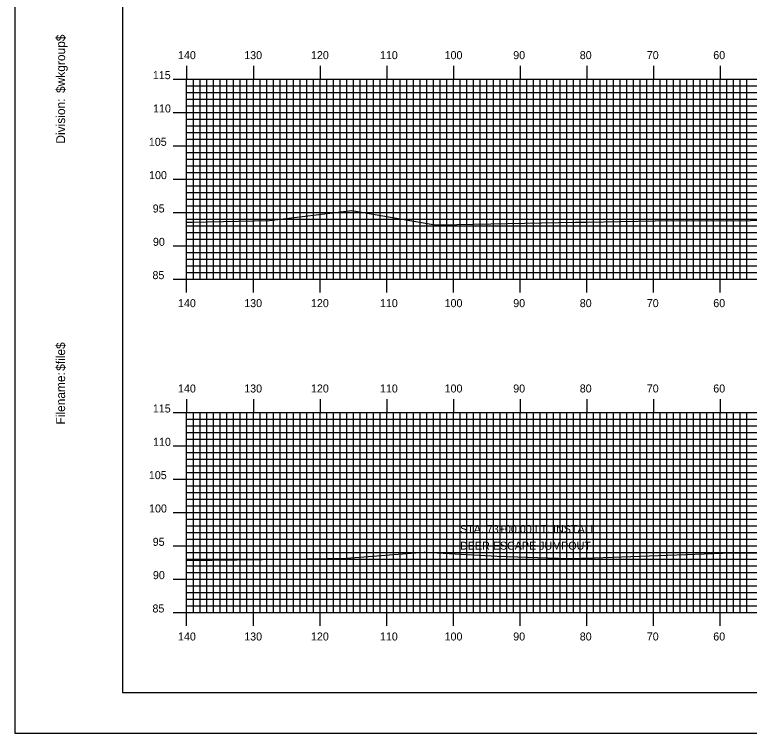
# Model space of a CAD drawing. Extents: x 1761004 to 1761347, y 442591 to 442811.
# Drawn here: x 1761003.9 to 1761114.1, y 442590.5 to 442698.3 of the extents above; entities that cross this region are included whole.
import ezdxf

# ---------------------------------------------------------------- set-up
doc = ezdxf.new("R2010")
doc.units = 0
for name, color, linetype in [('BORDER', 7, 'Continuous'), ('D_Text_Standard', 7, 'Continuous'), ('H_V ANNOTATION', 7, 'Continuous'), ('MAJOR', 7, 'Continuous'), ('MINOR', 7, 'Continuous'), ('PLOT BOUNDARY', 7, 'Continuous'), ('S_Roadway_Centerline', 7, 'Continuous')]:
    doc.layers.add(name, color=color, linetype=linetype)

msp = doc.modelspace()

# ---------------------------------------------------------------- linework, layer by layer
at = {"layer": 'BORDER'}
msp.add_lwpolyline([(1761020.13, 442596.67), (1761340.13, 442596.67), (1761340.13, 442806.67), (1761020.13, 442806.67)], close=True, dxfattribs=at)
at = {"layer": 'MAJOR'}
for p, q in [((1761029.73, 442690.67), (1761029.73, 442688.67)), ((1761039.73, 442690.67), (1761039.73, 442688.67)), ((1761049.73, 442690.67), (1761049.73, 442688.67)), ((1761059.73, 442690.67), (1761059.73, 442688.67)), ((1761069.73, 442690.67), (1761069.73, 442688.67)), ((1761079.73, 442690.67), (1761079.73, 442688.67)), ((1761089.73, 442690.67), (1761089.73, 442688.67)), ((1761099.73, 442690.67), (1761099.73, 442688.67)), ((1761109.73, 442690.67), (1761109.73, 442688.67)), ((1761027.72, 442688.67), (1761029.73, 442688.67)), ((1761029.73, 442688.67), (1761309.73, 442688.67)), ((1761029.73, 442658.67), (1761029.73, 442688.67)), ((1761029.73, 442658.67), (1761029.73, 442688.67)), ((1761029.73, 442688.67), (1761309.73, 442688.67)), ((1761039.73, 442658.67), (1761039.73, 442688.67)), ((1761049.73, 442658.67), (1761049.73, 442688.67)), ((1761059.73, 442658.67), (1761059.73, 442688.67)), ((1761069.73, 442658.67), (1761069.73, 442688.67)), ((1761079.73, 442658.67), (1761079.73, 442688.67)), ((1761089.73, 442658.67), (1761089.73, 442688.67)), ((1761099.73, 442658.67), (1761099.73, 442688.67)), ((1761109.73, 442658.67), (1761109.73, 442688.67)), ((1761027.72, 442683.67), (1761029.73, 442683.67)), ((1761029.73, 442683.67), (1761309.73, 442683.67)), ((1761027.72, 442678.67), (1761029.73, 442678.67)), ((1761029.73, 442678.67), (1761309.73, 442678.67)), ((1761027.72, 442673.67), (1761029.73, 442673.67)), ((1761029.73, 442673.67), (1761309.73, 442673.67)), ((1761027.72, 442668.67), (1761029.73, 442668.67)), ((1761029.73, 442668.67), (1761309.73, 442668.67)), ((1761027.72, 442663.67), (1761029.73, 442663.67)), ((1761029.73, 442663.67), (1761309.73, 442663.67)), ((1761027.72, 442658.67), (1761029.73, 442658.67)), ((1761029.73, 442658.67), (1761309.73, 442658.67)), ((1761029.73, 442658.67), (1761309.73, 442658.67)), ((1761029.73, 442656.66), (1761029.73, 442658.67)), ((1761039.73, 442656.66), (1761039.73, 442658.67)), ((1761049.73, 442656.66), (1761049.73, 442658.67)), ((1761059.73, 442656.66), (1761059.73, 442658.67)), ((1761069.73, 442656.66), (1761069.73, 442658.67)), ((1761079.73, 442656.66), (1761079.73, 442658.67)), ((1761089.73, 442656.66), (1761089.73, 442658.67)), ((1761099.73, 442656.66), (1761099.73, 442658.67)), ((1761109.73, 442656.66), (1761109.73, 442658.67)), ((1761029.73, 442640.67), (1761029.73, 442638.67)), ((1761039.73, 442640.67), (1761039.73, 442638.67)), ((1761049.73, 442640.67), (1761049.73, 442638.67)), ((1761059.73, 442640.67), (1761059.73, 442638.67)), ((1761069.73, 442640.67), (1761069.73, 442638.67)), ((1761079.73, 442640.67), (1761079.73, 442638.67)), ((1761089.73, 442640.67), (1761089.73, 442638.67)), ((1761099.73, 442640.67), (1761099.73, 442638.67)), ((1761109.73, 442640.67), (1761109.73, 442638.67)), ((1761027.72, 442638.67), (1761029.73, 442638.67)), ((1761029.73, 442638.67), (1761309.73, 442638.67)), ((1761029.73, 442608.67), (1761029.73, 442638.67)), ((1761029.73, 442608.67), (1761029.73, 442638.67)), ((1761029.73, 442638.67), (1761309.73, 442638.67)), ((1761039.73, 442608.67), (1761039.73, 442638.67)), ((1761049.73, 442608.67), (1761049.73, 442638.67)), ((1761059.73, 442608.67), (1761059.73, 442638.67)), ((1761069.73, 442608.67), (1761069.73, 442638.67)), ((1761079.73, 442608.67), (1761079.73, 442638.67)), ((1761089.73, 442608.67), (1761089.73, 442638.67)), ((1761099.73, 442608.67), (1761099.73, 442638.67)), ((1761109.73, 442608.67), (1761109.73, 442638.67)), ((1761027.72, 442633.67), (1761029.73, 442633.67)), ((1761029.73, 442633.67), (1761309.73, 442633.67)), ((1761027.72, 442628.67), (1761029.73, 442628.67)), ((1761029.73, 442628.67), (1761309.73, 442628.67)), ((1761027.72, 442623.67), (1761029.73, 442623.67)), ((1761029.73, 442623.67), (1761309.73, 442623.67)), ((1761027.72, 442618.67), (1761029.73, 442618.67)), ((1761029.73, 442618.67), (1761309.73, 442618.67)), ((1761027.72, 442613.67), (1761029.73, 442613.67)), ((1761029.73, 442613.67), (1761309.73, 442613.67)), ((1761027.72, 442608.67), (1761029.73, 442608.67)), ((1761029.73, 442608.67), (1761309.73, 442608.67)), ((1761029.73, 442608.67), (1761309.73, 442608.67)), ((1761029.73, 442606.66), (1761029.73, 442608.67)), ((1761039.73, 442606.66), (1761039.73, 442608.67)), ((1761049.73, 442606.66), (1761049.73, 442608.67)), ((1761059.73, 442606.66), (1761059.73, 442608.67)), ((1761069.73, 442606.66), (1761069.73, 442608.67)), ((1761079.73, 442606.66), (1761079.73, 442608.67)), ((1761089.73, 442606.66), (1761089.73, 442608.67)), ((1761099.73, 442606.66), (1761099.73, 442608.67)), ((1761109.73, 442606.66), (1761109.73, 442608.67))]:
    msp.add_line(p, q, dxfattribs=at)
at = {"layer": 'MINOR'}
for p, q in [((1761030.73, 442658.67), (1761030.73, 442688.67)), ((1761031.73, 442658.67), (1761031.73, 442688.67)), ((1761032.73, 442658.67), (1761032.73, 442688.67)), ((1761033.73, 442658.67), (1761033.73, 442688.67)), ((1761034.73, 442658.67), (1761034.73, 442688.67)), ((1761035.73, 442658.67), (1761035.73, 442688.67)), ((1761036.73, 442658.67), (1761036.73, 442688.67)), ((1761037.73, 442658.67), (1761037.73, 442688.67)), ((1761038.73, 442658.67), (1761038.73, 442688.67)), ((1761040.73, 442658.67), (1761040.73, 442688.67)), ((1761041.73, 442658.67), (1761041.73, 442688.67)), ((1761042.73, 442658.67), (1761042.73, 442688.67)), ((1761043.73, 442658.67), (1761043.73, 442688.67)), ((1761044.73, 442658.67), (1761044.73, 442688.67)), ((1761045.73, 442658.67), (1761045.73, 442688.67)), ((1761046.73, 442658.67), (1761046.73, 442688.67)), ((1761047.73, 442658.67), (1761047.73, 442688.67)), ((1761048.73, 442658.67), (1761048.73, 442688.67)), ((1761050.73, 442658.67), (1761050.73, 442688.67)), ((1761051.73, 442658.67), (1761051.73, 442688.67)), ((1761052.73, 442658.67), (1761052.73, 442688.67)), ((1761053.73, 442658.67), (1761053.73, 442688.67)), ((1761054.73, 442658.67), (1761054.73, 442688.67)), ((1761055.73, 442658.67), (1761055.73, 442688.67)), ((1761056.73, 442658.67), (1761056.73, 442688.67)), ((1761057.73, 442658.67), (1761057.73, 442688.67)), ((1761058.73, 442658.67), (1761058.73, 442688.67)), ((1761060.73, 442658.67), (1761060.73, 442688.67)), ((1761061.73, 442658.67), (1761061.73, 442688.67)), ((1761062.73, 442658.67), (1761062.73, 442688.67)), ((1761063.73, 442658.67), (1761063.73, 442688.67)), ((1761064.73, 442658.67), (1761064.73, 442688.67)), ((1761065.73, 442658.67), (1761065.73, 442688.67)), ((1761066.73, 442658.67), (1761066.73, 442688.67)), ((1761067.73, 442658.67), (1761067.73, 442688.67)), ((1761068.73, 442658.67), (1761068.73, 442688.67)), ((1761070.73, 442658.67), (1761070.73, 442688.67)), ((1761071.73, 442658.67), (1761071.73, 442688.67)), ((1761072.73, 442658.67), (1761072.73, 442688.67)), ((1761073.73, 442658.67), (1761073.73, 442688.67)), ((1761074.73, 442658.67), (1761074.73, 442688.67)), ((1761075.73, 442658.67), (1761075.73, 442688.67)), ((1761076.73, 442658.67), (1761076.73, 442688.67)), ((1761077.73, 442658.67), (1761077.73, 442688.67)), ((1761078.73, 442658.67), (1761078.73, 442688.67)), ((1761080.73, 442658.67), (1761080.73, 442688.67)), ((1761081.73, 442658.67), (1761081.73, 442688.67)), ((1761082.73, 442658.67), (1761082.73, 442688.67)), ((1761083.73, 442658.67), (1761083.73, 442688.67)), ((1761084.73, 442658.67), (1761084.73, 442688.67)), ((1761085.73, 442658.67), (1761085.73, 442688.67)), ((1761086.73, 442658.67), (1761086.73, 442688.67)), ((1761087.73, 442658.67), (1761087.73, 442688.67)), ((1761088.73, 442658.67), (1761088.73, 442688.67)), ((1761090.73, 442658.67), (1761090.73, 442688.67)), ((1761091.73, 442658.67), (1761091.73, 442688.67)), ((1761092.73, 442658.67), (1761092.73, 442688.67)), ((1761093.73, 442658.67), (1761093.73, 442688.67)), ((1761094.73, 442658.67), (1761094.73, 442688.67)), ((1761095.73, 442658.67), (1761095.73, 442688.67)), ((1761096.73, 442658.67), (1761096.73, 442688.67)), ((1761097.73, 442658.67), (1761097.73, 442688.67)), ((1761098.73, 442658.67), (1761098.73, 442688.67)), ((1761100.73, 442658.67), (1761100.73, 442688.67)), ((1761101.73, 442658.67), (1761101.73, 442688.67)), ((1761102.73, 442658.67), (1761102.73, 442688.67)), ((1761103.73, 442658.67), (1761103.73, 442688.67)), ((1761104.73, 442658.67), (1761104.73, 442688.67)), ((1761105.73, 442658.67), (1761105.73, 442688.67)), ((1761106.73, 442658.67), (1761106.73, 442688.67)), ((1761107.73, 442658.67), (1761107.73, 442688.67)), ((1761108.73, 442658.67), (1761108.73, 442688.67)), ((1761110.73, 442658.67), (1761110.73, 442688.67)), ((1761111.73, 442658.67), (1761111.73, 442688.67)), ((1761112.73, 442658.67), (1761112.73, 442688.67)), ((1761113.73, 442658.67), (1761113.73, 442688.67)), ((1761029.73, 442687.67), (1761309.73, 442687.67)), ((1761029.73, 442687.67), (1761031.73, 442687.67)), ((1761029.73, 442686.67), (1761309.73, 442686.67)), ((1761029.73, 442686.67), (1761031.73, 442686.67)), ((1761029.73, 442685.67), (1761309.73, 442685.67)), ((1761029.73, 442685.67), (1761031.73, 442685.67)), ((1761029.73, 442684.67), (1761309.73, 442684.67)), ((1761029.73, 442684.67), (1761031.73, 442684.67)), ((1761029.73, 442682.67), (1761309.73, 442682.67)), ((1761029.73, 442682.67), (1761031.73, 442682.67)), ((1761029.73, 442681.67), (1761309.73, 442681.67)), ((1761029.73, 442681.67), (1761031.73, 442681.67)), ((1761029.73, 442680.67), (1761309.73, 442680.67)), ((1761029.73, 442680.67), (1761031.73, 442680.67)), ((1761029.73, 442679.67), (1761309.73, 442679.67)), ((1761029.73, 442679.67), (1761031.73, 442679.67)), ((1761029.73, 442677.67), (1761309.73, 442677.67)), ((1761029.73, 442677.67), (1761031.73, 442677.67)), ((1761029.73, 442676.67), (1761309.73, 442676.67)), ((1761029.73, 442676.67), (1761031.73, 442676.67)), ((1761029.73, 442675.67), (1761309.73, 442675.67)), ((1761029.73, 442675.67), (1761031.73, 442675.67)), ((1761029.73, 442674.67), (1761309.73, 442674.67)), ((1761029.73, 442674.67), (1761031.73, 442674.67)), ((1761029.73, 442672.67), (1761309.73, 442672.67)), ((1761029.73, 442672.67), (1761031.73, 442672.67)), ((1761029.73, 442671.67), (1761309.73, 442671.67)), ((1761029.73, 442671.67), (1761031.73, 442671.67)), ((1761029.73, 442670.67), (1761309.73, 442670.67)), ((1761029.73, 442670.67), (1761031.73, 442670.67)), ((1761029.73, 442669.67), (1761309.73, 442669.67)), ((1761029.73, 442669.67), (1761031.73, 442669.67)), ((1761029.73, 442667.67), (1761309.73, 442667.67)), ((1761029.73, 442667.67), (1761031.73, 442667.67)), ((1761029.73, 442666.67), (1761309.73, 442666.67)), ((1761029.73, 442666.67), (1761031.73, 442666.67)), ((1761029.73, 442665.67), (1761309.73, 442665.67)), ((1761029.73, 442665.67), (1761031.73, 442665.67)), ((1761029.73, 442664.67), (1761309.73, 442664.67)), ((1761029.73, 442664.67), (1761031.73, 442664.67)), ((1761029.73, 442662.67), (1761309.73, 442662.67)), ((1761029.73, 442662.67), (1761031.73, 442662.67)), ((1761029.73, 442661.67), (1761309.73, 442661.67)), ((1761029.73, 442661.67), (1761031.73, 442661.67)), ((1761029.73, 442660.67), (1761309.73, 442660.67)), ((1761029.73, 442660.67), (1761031.73, 442660.67)), ((1761029.73, 442659.67), (1761309.73, 442659.67)), ((1761029.73, 442659.67), (1761031.73, 442659.67)), ((1761030.73, 442608.67), (1761030.73, 442638.67)), ((1761031.73, 442608.67), (1761031.73, 442638.67)), ((1761032.73, 442608.67), (1761032.73, 442638.67)), ((1761033.73, 442608.67), (1761033.73, 442638.67)), ((1761034.73, 442608.67), (1761034.73, 442638.67)), ((1761035.73, 442608.67), (1761035.73, 442638.67)), ((1761036.73, 442608.67), (1761036.73, 442638.67)), ((1761037.73, 442608.67), (1761037.73, 442638.67)), ((1761038.73, 442608.67), (1761038.73, 442638.67)), ((1761040.73, 442608.67), (1761040.73, 442638.67)), ((1761041.73, 442608.67), (1761041.73, 442638.67)), ((1761042.73, 442608.67), (1761042.73, 442638.67)), ((1761043.73, 442608.67), (1761043.73, 442638.67)), ((1761044.73, 442608.67), (1761044.73, 442638.67)), ((1761045.73, 442608.67), (1761045.73, 442638.67)), ((1761046.73, 442608.67), (1761046.73, 442638.67)), ((1761047.73, 442608.67), (1761047.73, 442638.67)), ((1761048.73, 442608.67), (1761048.73, 442638.67)), ((1761050.73, 442608.67), (1761050.73, 442638.67)), ((1761051.73, 442608.67), (1761051.73, 442638.67)), ((1761052.73, 442608.67), (1761052.73, 442638.67)), ((1761053.73, 442608.67), (1761053.73, 442638.67)), ((1761054.73, 442608.67), (1761054.73, 442638.67)), ((1761055.73, 442608.67), (1761055.73, 442638.67)), ((1761056.73, 442608.67), (1761056.73, 442638.67)), ((1761057.73, 442608.67), (1761057.73, 442638.67)), ((1761058.73, 442608.67), (1761058.73, 442638.67)), ((1761060.73, 442608.67), (1761060.73, 442638.67)), ((1761061.73, 442608.67), (1761061.73, 442638.67)), ((1761062.73, 442608.67), (1761062.73, 442638.67)), ((1761063.73, 442608.67), (1761063.73, 442638.67)), ((1761064.73, 442608.67), (1761064.73, 442638.67)), ((1761065.73, 442608.67), (1761065.73, 442638.67)), ((1761066.73, 442608.67), (1761066.73, 442638.67)), ((1761067.73, 442608.67), (1761067.73, 442638.67)), ((1761068.73, 442608.67), (1761068.73, 442638.67)), ((1761070.73, 442608.67), (1761070.73, 442638.67)), ((1761071.73, 442608.67), (1761071.73, 442638.67)), ((1761072.73, 442608.67), (1761072.73, 442638.67)), ((1761073.73, 442608.67), (1761073.73, 442638.67)), ((1761074.73, 442608.67), (1761074.73, 442638.67)), ((1761075.73, 442608.67), (1761075.73, 442638.67)), ((1761076.73, 442608.67), (1761076.73, 442638.67)), ((1761077.73, 442608.67), (1761077.73, 442638.67)), ((1761078.73, 442608.67), (1761078.73, 442638.67)), ((1761080.73, 442608.67), (1761080.73, 442638.67)), ((1761081.73, 442608.67), (1761081.73, 442638.67)), ((1761082.73, 442608.67), (1761082.73, 442638.67)), ((1761083.73, 442608.67), (1761083.73, 442638.67)), ((1761084.73, 442608.67), (1761084.73, 442638.67)), ((1761085.73, 442608.67), (1761085.73, 442638.67)), ((1761086.73, 442608.67), (1761086.73, 442638.67)), ((1761087.73, 442608.67), (1761087.73, 442638.67)), ((1761088.73, 442608.67), (1761088.73, 442638.67)), ((1761090.73, 442608.67), (1761090.73, 442638.67)), ((1761091.73, 442608.67), (1761091.73, 442638.67)), ((1761092.73, 442608.67), (1761092.73, 442638.67)), ((1761093.73, 442608.67), (1761093.73, 442638.67)), ((1761094.73, 442608.67), (1761094.73, 442638.67)), ((1761095.73, 442608.67), (1761095.73, 442638.67)), ((1761096.73, 442608.67), (1761096.73, 442638.67)), ((1761097.73, 442608.67), (1761097.73, 442638.67)), ((1761098.73, 442608.67), (1761098.73, 442638.67)), ((1761100.73, 442608.67), (1761100.73, 442638.67)), ((1761101.73, 442608.67), (1761101.73, 442638.67)), ((1761102.73, 442608.67), (1761102.73, 442638.67)), ((1761103.73, 442608.67), (1761103.73, 442638.67)), ((1761104.73, 442608.67), (1761104.73, 442638.67)), ((1761105.73, 442608.67), (1761105.73, 442638.67)), ((1761106.73, 442608.67), (1761106.73, 442638.67)), ((1761107.73, 442608.67), (1761107.73, 442638.67)), ((1761108.73, 442608.67), (1761108.73, 442638.67)), ((1761110.73, 442608.67), (1761110.73, 442638.67)), ((1761111.73, 442608.67), (1761111.73, 442638.67)), ((1761112.73, 442608.67), (1761112.73, 442638.67)), ((1761113.73, 442608.67), (1761113.73, 442638.67)), ((1761029.73, 442637.67), (1761309.73, 442637.67)), ((1761029.73, 442637.67), (1761031.73, 442637.67)), ((1761029.73, 442636.67), (1761309.73, 442636.67)), ((1761029.73, 442636.67), (1761031.73, 442636.67)), ((1761029.73, 442635.67), (1761309.73, 442635.67)), ((1761029.73, 442635.67), (1761031.73, 442635.67)), ((1761029.73, 442634.67), (1761309.73, 442634.67)), ((1761029.73, 442634.67), (1761031.73, 442634.67)), ((1761029.73, 442632.67), (1761309.73, 442632.67)), ((1761029.73, 442632.67), (1761031.73, 442632.67)), ((1761029.73, 442631.67), (1761309.73, 442631.67)), ((1761029.73, 442631.67), (1761031.73, 442631.67)), ((1761029.73, 442630.67), (1761309.73, 442630.67)), ((1761029.73, 442630.67), (1761031.73, 442630.67)), ((1761029.73, 442629.67), (1761309.73, 442629.67)), ((1761029.73, 442629.67), (1761031.73, 442629.67)), ((1761029.73, 442627.67), (1761309.73, 442627.67)), ((1761029.73, 442627.67), (1761031.73, 442627.67)), ((1761029.73, 442626.67), (1761309.73, 442626.67)), ((1761029.73, 442626.67), (1761031.73, 442626.67)), ((1761029.73, 442625.67), (1761309.73, 442625.67)), ((1761029.73, 442625.67), (1761031.73, 442625.67)), ((1761029.73, 442624.67), (1761309.73, 442624.67)), ((1761029.73, 442624.67), (1761031.73, 442624.67)), ((1761029.73, 442622.67), (1761309.73, 442622.67)), ((1761029.73, 442622.67), (1761031.73, 442622.67)), ((1761029.73, 442621.67), (1761309.73, 442621.67)), ((1761029.73, 442621.67), (1761031.73, 442621.67)), ((1761029.73, 442620.67), (1761309.73, 442620.67)), ((1761029.73, 442620.67), (1761031.73, 442620.67)), ((1761029.73, 442619.67), (1761309.73, 442619.67)), ((1761029.73, 442619.67), (1761031.73, 442619.67)), ((1761029.73, 442617.67), (1761309.73, 442617.67)), ((1761029.73, 442617.67), (1761031.73, 442617.67)), ((1761029.73, 442616.67), (1761309.73, 442616.67)), ((1761029.73, 442616.67), (1761031.73, 442616.67)), ((1761029.73, 442615.67), (1761309.73, 442615.67)), ((1761029.73, 442615.67), (1761031.73, 442615.67)), ((1761029.73, 442614.67), (1761309.73, 442614.67)), ((1761029.73, 442614.67), (1761031.73, 442614.67)), ((1761029.73, 442612.67), (1761309.73, 442612.67)), ((1761029.73, 442612.67), (1761031.73, 442612.67)), ((1761029.73, 442611.67), (1761309.73, 442611.67)), ((1761029.73, 442611.67), (1761031.73, 442611.67)), ((1761029.73, 442610.67), (1761309.73, 442610.67)), ((1761029.73, 442610.67), (1761031.73, 442610.67)), ((1761029.73, 442609.67), (1761309.73, 442609.67)), ((1761029.73, 442609.67), (1761031.73, 442609.67))]:
    msp.add_line(p, q, dxfattribs=at)
at = {"layer": 'PLOT BOUNDARY'}
msp.add_lwpolyline([(1761003.94, 442590.55), (1761343.94, 442590.55), (1761343.94, 442810.55), (1761003.94, 442810.55)], close=True, dxfattribs=at)
at = {"layer": 'S_Roadway_Centerline'}
for points in [[(1761029.73, 442667.21), (1761030.55, 442667.21), (1761042.13, 442667.45), (1761042.14, 442667.45), (1761042.15, 442667.45), (1761054.5, 442668.98), (1761066.71, 442666.85), (1761067.18, 442666.8), (1761067.71, 442666.8), (1761088.06, 442667.2), (1761088.96, 442667.24), (1761089.68, 442667.22), (1761099.97, 442667.41), (1761111.24, 442667.45), (1761112.76, 442667.42), (1761132.26, 442668.06)], [(1761029.73, 442616.46), (1761041.03, 442616.64), (1761041.39, 442616.65), (1761041.79, 442616.64), (1761053.69, 442616.81), (1761065.33, 442617.71), (1761065.43, 442617.72), (1761065.51, 442617.71), (1761076.28, 442617.12), (1761086.93, 442616.75), (1761090.84, 442616.86), (1761110.11, 442617.56), (1761112.77, 442617.6), (1761122.62, 442617.53)]]:
    msp.add_lwpolyline(points, dxfattribs=at)

# ---------------------------------------------------------------- texts
at = {"layer": 'BORDER'}
for s, p in [('$wkgroup$', (1761011.5, 442686.6)), ('Division:', (1761011.5, 442679)), ('$file$', (1761011.5, 442644.92)), ('Filename:', (1761011.5, 442636.86))]:
    msp.add_text(s, height=1.339, rotation=90, dxfattribs=at).set_placement(p)
at = {"layer": 'D_Text_Standard'}
for s, p in [('STA. 73+00.00 LT. INSTALL ', (1761070.73, 442620.59)), ('DEER ESCAPE JUMPOUT', (1761070.73, 442618.09))]:
    msp.add_text(s, height=1.2, dxfattribs=at).set_placement(p)
at = {"layer": 'H_V ANNOTATION'}
for s, p in [('140', (1761028.43, 442691.67)), ('130', (1761038.36, 442691.67)), ('120', (1761048.37, 442691.67)), ('110', (1761058.71, 442691.67)), ('100', (1761068.41, 442691.67)), ('90', (1761078.7, 442691.67)), ('80', (1761088.68, 442691.67)), ('70', (1761098.73, 442691.67)), ('60', (1761108.7, 442691.67)), ('115', (1761024.66, 442688.67)), ('110', (1761024.69, 442683.67)), ('105', (1761024.06, 442678.67)), ('100', (1761024.09, 442673.67)), ('95', (1761024.64, 442668.67)), ('90', (1761024.67, 442663.67)), ('85', (1761024.6, 442658.67)), ('140', (1761028.43, 442654.47)), ('130', (1761038.36, 442654.47)), ('120', (1761048.37, 442654.47)), ('110', (1761058.71, 442654.47)), ('100', (1761068.41, 442654.47)), ('90', (1761078.7, 442654.47)), ('80', (1761088.68, 442654.47)), ('70', (1761098.73, 442654.47)), ('60', (1761108.7, 442654.47)), ('140', (1761028.43, 442641.67)), ('130', (1761038.36, 442641.67)), ('120', (1761048.37, 442641.67)), ('110', (1761058.71, 442641.67)), ('100', (1761068.41, 442641.67)), ('90', (1761078.7, 442641.67)), ('80', (1761088.68, 442641.67)), ('70', (1761098.73, 442641.67)), ('60', (1761108.7, 442641.67)), ('115', (1761024.66, 442638.67)), ('110', (1761024.69, 442633.67)), ('105', (1761024.06, 442628.67)), ('100', (1761024.09, 442623.67)), ('95', (1761024.64, 442618.67)), ('90', (1761024.67, 442613.67)), ('85', (1761024.6, 442608.67)), ('140', (1761028.43, 442604.47)), ('130', (1761038.36, 442604.47)), ('120', (1761048.37, 442604.47)), ('110', (1761058.71, 442604.47)), ('100', (1761068.41, 442604.47)), ('90', (1761078.7, 442604.47)), ('80', (1761088.68, 442604.47)), ('70', (1761098.73, 442604.47)), ('60', (1761108.7, 442604.47))]:
    msp.add_text(s, height=1.2, dxfattribs=at).set_placement(p)
at = {"layer": 'MAJOR'}
for p in [(1761029.72, 442658.67), (1761029.72, 442608.67)]:
    msp.add_text('-', height=0.012, dxfattribs=at).set_placement(p)

doc.saveas('drawing.dxf')
